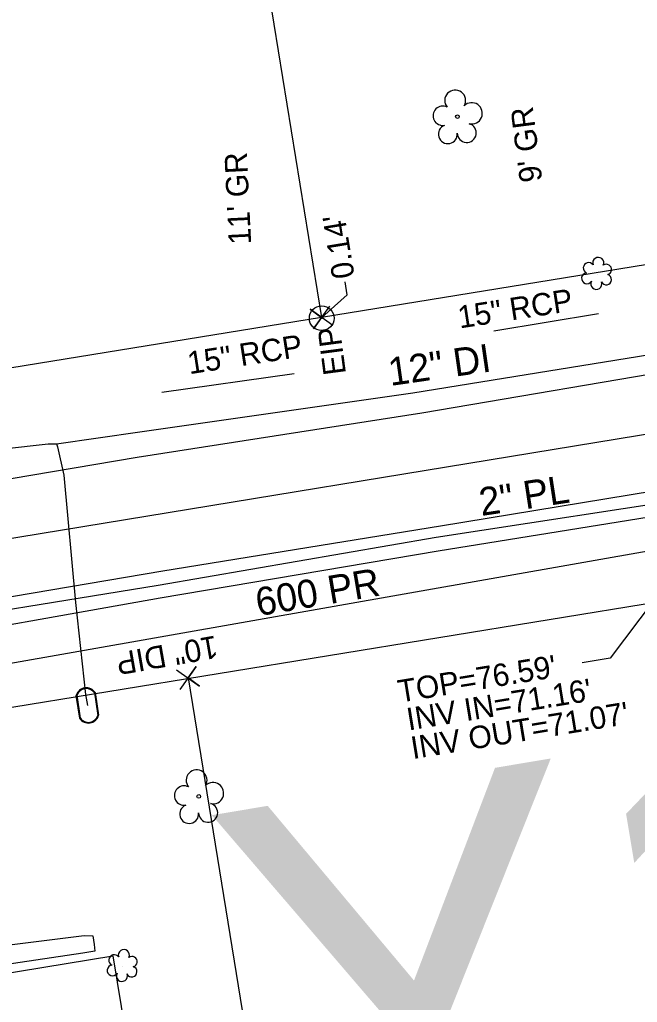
# Model space of a CAD drawing. Extents: x 2364404 to 2371833, y 798876 to 809754.
# Drawn here: x 2368683.2 to 2368793.3, y 807917.2 to 808092.3 of the extents above; entities that cross this region are included whole.
import ezdxf

# ---------------------------------------------------------------- set-up
doc = ezdxf.new("R2010")
doc.units = 0
for name, color, linetype in [('Exist Building', 7, 'Continuous'), ('Exist Horizontal Alignment Direction Label', 7, 'Continuous'), ('Exist Property Corner CELL', 7, 'Continuous'), ('Exist Property Iron Pin CELL', 7, 'Continuous'), ('Exist Property Iron Pin Text', 7, 'Continuous'), ('Exist Property Line', 7, 'Continuous'), ('Exist Property Line Leader', 7, 'Continuous'), ('Exist Property Line Text', 7, 'Continuous'), ('Exist Right of Way Line', 7, 'Continuous'), ('Exist Roads EOP', 7, 'Continuous'), ('Exist Roads Soil Text', 7, 'Continuous'), ('Exist Structure Minor Pipes RCP 15 Inch', 7, 'Continuous'), ('Exist Structure Minor Pipes RCP 15 Inch Text', 7, 'Continuous'), ('Exist Utilities Gas UG Line SUE LOS B', 7, 'Continuous'), ('Exist Utilities Gas UG Line SUE LOS B Text', 7, 'Continuous'), ('Exist Utilities Sanitary Sewer Manhole Leader', 7, 'Continuous'), ('Exist Utilities Sanitary Sewer Manhole Top Elevation', 7, 'Continuous'), ('Exist Utilities Sanitary Sewer UG Line', 7, 'Continuous'), ('Exist Utilities Sanitary Sewer UG Line Invert Elevation', 7, 'Continuous'), ('Exist Utilities Sanitary Sewer UG Line Text', 7, 'Continuous'), ('Exist Utilities Telephone UG Cable SUE LOS C', 7, 'Continuous'), ('Exist Utilities Telephone UG Cable SUE LOS C Text', 7, 'Continuous'), ('Exist Utilities Water Meter CELL', 7, 'Continuous'), ('Exist Utilities Water UG Line SUE LOS B', 7, 'Continuous'), ('Exist Utilities Water UG Line SUE LOS B Text', 7, 'Continuous'), ('Exist Vegetation Hedge Row', 7, 'Continuous'), ('Exist Vegetation Shrub CELL', 7, 'Continuous'), ('Exist Vegetation Tree CELL', 7, 'Continuous'), ('Prop Horizontal Alignment', 7, 'Continuous')]:
    doc.layers.add(name, color=color, linetype=linetype)

msp = doc.modelspace()

# ---------------------------------------------------------------- linework, layer by layer
at = {"layer": 'Exist Building'}
msp.add_lwpolyline([(2368704.34, 807898.02), (2368640.13, 807887.48), (2368635.66, 807914.69), (2368658.33, 807918.42), (2368657.75, 807921.93), (2368674.26, 807924.65), (2368674.8, 807921.37), (2368699.83, 807925.48)], close=True, dxfattribs=at)
at = {"layer": 'Exist Property Corner CELL'}
for p, q in [((2368737.05, 808039.21), (2368737.05, 808039.21)), ((2368713.24, 807974.97), (2368713.24, 807974.97))]:
    msp.add_line(p, q, dxfattribs=at)
for points in [[(2368739.08, 808037.75), (2368735.02, 808040.67), (2368737.05, 808039.21), (2368735.59, 808037.18), (2368738.51, 808041.24)], [(2368711.21, 807976.43), (2368715.27, 807973.51), (2368713.24, 807974.97), (2368714.7, 807977), (2368711.78, 807972.94)]]:
    msp.add_lwpolyline(points, dxfattribs=at)
at = {"layer": 'Exist Property Iron Pin CELL'}
for radius in [2.2, 0.0707]:
    msp.add_circle((2368737.07, 808039.07), radius, dxfattribs=at)
at = {"layer": 'Exist Property Line'}
for p, q in [((2368696.87, 808285.98), (2368737.05, 808039.21)), ((2368737.05, 808039.21), (2368737.07, 808039.07)), ((2368713.24, 807974.97), (2368748.74, 807757.77))]:
    msp.add_line(p, q, dxfattribs=at)
at = {"layer": 'Exist Property Line Leader'}
msp.add_lwpolyline([(2368737.09, 808039.23), (2368741.62, 808043.26), (2368741.25, 808045.55)], dxfattribs=at)
at = {"layer": 'Exist Right of Way Line'}
for p, q in [((2368966.1, 808076.49), (2368408.25, 807985.69)), ((2368975.69, 808017.56), (2368415.81, 807926.44))]:
    msp.add_line(p, q, dxfattribs=at)
at = {"layer": 'Exist Roads EOP'}
for points in [[(2368541.68, 807987.78), (2368591.98, 807995.84), (2368655.32, 808006.07), (2368704.17, 808014.3), (2368754.94, 808022.2), (2368804.52, 808030.63), (2368845.71, 808037.37), (2368893.98, 808045.18)], [(2368496.73, 807956.25), (2368544.8, 807964.78), (2368595.22, 807974.76), (2368620.07, 807978.44), (2368644.18, 807982.77), (2368658.61, 807985.55), (2368708.73, 807994.07), (2368758.23, 808002.08), (2368808.85, 808010.39), (2368820.54, 808011.83), (2368846.02, 808015.63), (2368897.31, 808024.64)]]:
    msp.add_lwpolyline(points, dxfattribs=at)
at = {"layer": 'Exist Structure Minor Pipes RCP 15 Inch'}
for p, q in [((2368767.76, 808036.8), (2368786.44, 808039.92)), ((2368732.19, 808029.17), (2368708.58, 808025.86))]:
    msp.add_line(p, q, dxfattribs=at)
at = {"layer": 'Exist Utilities Gas UG Line SUE LOS B'}
msp.add_lwpolyline([(2368407.49, 807900.26), (2368407.83, 807902.19), (2368408.5, 807903.92), (2368408.48, 807906.42), (2368409.65, 807914.64), (2368412.56, 807921.31), (2368413.42, 807922.79), (2368414.43, 807924.35), (2368420.02, 807930.36), (2368432.93, 807938.29), (2368511.16, 807956.83), (2368547.75, 807963.81), (2368550.91, 807964.29), (2368560.32, 807966.83), (2368577.66, 807970.81), (2368609.45, 807976.23), (2368658.87, 807983.56), (2368707.95, 807991.52), (2368757.5, 808000.06), (2368807.07, 808007.66), (2368820.71, 808009.46), (2368856.81, 808014.26), (2368905.45, 808022.91)], dxfattribs=at)
at = {"layer": 'Exist Utilities Sanitary Sewer Manhole Leader'}
msp.add_lwpolyline([(2368804.16, 807999.27), (2368788.52, 807978.49), (2368783.51, 807977.67)], dxfattribs=at)
at = {"layer": 'Exist Utilities Sanitary Sewer UG Line'}
msp.add_line((2368448.77, 807936.62), (2368803.21, 807999.04), dxfattribs=at)
at = {"layer": 'Exist Utilities Telephone UG Cable SUE LOS C'}
msp.add_lwpolyline([(2368614.19, 807962.49), (2368614.48, 807964.11), (2368617.51, 807973.27), (2368659.45, 807980.57), (2368708.28, 807989.23), (2368757.83, 807997.6), (2368804.31, 808005.12), (2368807.97, 807999.56), (2368809.5, 807994.04), (2368810.63, 807992.57), (2368810.63, 807992.57), (2368811.3, 807991)], dxfattribs=at)
at = {"layer": 'Exist Utilities Water Meter CELL'}
msp.add_line((2368695.31, 807970.08), (2368695.31, 807970.08), dxfattribs=at)
for points in [[(2368693.93, 807967.81), (2368693.32, 807971.87)], [(2368694.07, 807967.83), (2368693.46, 807971.89)], [(2368696.55, 807972.33), (2368697.16, 807968.3)], [(2368696.69, 807972.35), (2368697.3, 807968.32)]]:
    msp.add_lwpolyline(points, dxfattribs=at)
for centre, radius, start, end in [((2368695.11, 807971.37), 1.86, 31.7443, 164.5457), ((2368695.11, 807971.36), 1.73, 33.8672, 162.3486), ((2368695.5, 807968.8), 1.86, 212.2146, 344.8747), ((2368695.51, 807968.79), 1.73, 213.6935, 343.4391)]:
    msp.add_arc(centre, radius, start, end, dxfattribs=at)
at = {"layer": 'Exist Utilities Water UG Line SUE LOS B'}
for points in [[(2368680.36, 808015.78), (2368688.31, 808016.66), (2368689.77, 808016.7), (2368704.64, 808018.8), (2368753.33, 808025.79), (2368803.62, 808033.92), (2368810.16, 808035.08), (2368853.48, 808041.6), (2368865.07, 808043.43), (2368901.86, 808048.89)], [(2368689.77, 808016.7), (2368689.98, 808016.15), (2368691.11, 808011.09), (2368693.17, 807988.41), (2368694.94, 807972.03), (2368695.31, 807970.08)]]:
    msp.add_lwpolyline(points, dxfattribs=at)
at = {"layer": 'Exist Vegetation Hedge Row'}
msp.add_lwpolyline([(2368656.22, 807925.92), (2368671.88, 807928.41), (2368673.37, 807928.15), (2368675.66, 807926.13), (2368677.58, 807926.92), (2368694.72, 807929.1), (2368696.28, 807929.04), (2368696.5, 807927.5), (2368696.62, 807926.31), (2368694.49, 807925.93), (2368677.67, 807923.43), (2368675.45, 807925.45), (2368658.21, 807922.85), (2368656.26, 807921.53), (2368655.31, 807921.7), (2368654.71, 807923.45), (2368654.63, 807924.61), (2368656.22, 807925.92)], dxfattribs=at)
at = {"layer": 'Exist Vegetation Shrub CELL'}
for p, q in [((2368786.15, 808046.89), (2368786.15, 808046.89)), ((2368701.58, 807923.56), (2368701.58, 807923.56))]:
    msp.add_line(p, q, dxfattribs=at)
for centre, radius, start, end in [((2368784.67, 808048.01), 0.968, 35.8908, 245.4216), ((2368786.38, 808048.93), 0.99, 334.8391, 200.4717), ((2368787.82, 808047.75), 0.929, 284.4567, 126.0861), ((2368784.35, 808046.18), 0.955, 95.1099, 327.9534), ((2368787.79, 808045.96), 0.937, 204.9913, 73.4601), ((2368786.02, 808045.2), 0.984, 151.2797, 21.387), ((2368701.81, 807925.6), 0.99, 334.8391, 200.4717), ((2368700.09, 807924.68), 0.968, 35.8908, 245.4216), ((2368703.25, 807924.42), 0.929, 284.4567, 126.0861), ((2368699.78, 807922.85), 0.955, 95.1099, 327.9534), ((2368701.45, 807921.87), 0.984, 151.2797, 21.387), ((2368703.21, 807922.63), 0.937, 204.9913, 73.4601)]:
    msp.add_arc(centre, radius, start, end, dxfattribs=at)
at = {"layer": 'Exist Vegetation Tree CELL'}
for p, q in [((2368761.26, 808074.99), (2368761.26, 808074.99)), ((2368715.15, 807953.85), (2368715.15, 807953.85))]:
    msp.add_line(p, q, dxfattribs=at)
for centre in [(2368761.26, 808074.99), (2368715.15, 807953.85)]:
    msp.add_circle(centre, 0.326, dxfattribs=at)
for centre, radius, start, end in [((2368760.87, 808077.87), 1.86, 330.1651, 219.7134), ((2368758.65, 808075.15), 1.73, 62.6636, 279.3457), ((2368763.81, 808075.58), 1.9, 257.1011, 134.1999), ((2368759.56, 808071.87), 1.69, 111.5671, 6.231), ((2368762.93, 808072.09), 1.7, 181.2822, 74.56), ((2368714.77, 807956.73), 1.86, 330.1651, 219.7134), ((2368712.55, 807954.01), 1.73, 62.6636, 279.3457), ((2368717.7, 807954.44), 1.9, 257.1011, 134.1999), ((2368713.45, 807950.73), 1.69, 111.5671, 6.231), ((2368716.83, 807950.95), 1.7, 181.2822, 74.56)]:
    msp.add_arc(centre, radius, start, end, dxfattribs=at)
at = {"layer": 'Prop Horizontal Alignment'}
msp.add_line((2368381.6, 807950.7), (2368895.64, 808034.91), dxfattribs=at)

# ---------------------------------------------------------------- texts
at = {"layer": 'Exist Horizontal Alignment Direction Label'}
msp.add_text('-Y15-', height=73.5, rotation=9.4942, dxfattribs=at).set_placement((2368695.22, 807872.27))
at = {"layer": 'Exist Property Iron Pin Text'}
msp.add_text('EIP', height=4, rotation=97.4798, dxfattribs=at).set_placement((2368741.41, 808029.2))
at = {"layer": 'Exist Property Line Text'}
msp.add_text("0.14'", height=4, rotation=99.2482, dxfattribs=at).set_placement((2368742.97, 808046.46))
at = {"layer": 'Exist Roads Soil Text'}
for s, rotation, p in [("9' GR", 97.3665, (2368776.41, 808063.56)), ("11' GR", 92.7743, (2368724.51, 808052.28))]:
    msp.add_text(s, height=4, rotation=rotation, dxfattribs=at).set_placement(p)
at = {"layer": 'Exist Structure Minor Pipes RCP 15 Inch Text'}
for p in [(2368761.67, 808037.24), (2368713.49, 808029.08)]:
    msp.add_text('15" RCP', height=4, rotation=8.8742, dxfattribs=at).set_placement(p)
at = {"layer": 'Exist Utilities Gas UG Line SUE LOS B Text'}
msp.add_text('2" PL', height=5, rotation=8.7175, dxfattribs=at).set_placement((2368765.54, 808003.82))
at = {"layer": 'Exist Utilities Sanitary Sewer Manhole Top Elevation'}
msp.add_text("TOP=76.59'", height=4, rotation=9.2445, dxfattribs=at).set_placement((2368750.99, 807970.57))
at = {"layer": 'Exist Utilities Sanitary Sewer UG Line Invert Elevation'}
for s, p in [("INV IN=71.16'", (2368752.56, 807965.6)), ("INV OUT=71.07'", (2368753.31, 807960.5))]:
    msp.add_text(s, height=4, rotation=9.2445, dxfattribs=at).set_placement(p)
at = {"layer": 'Exist Utilities Sanitary Sewer UG Line Text'}
msp.add_text('10" DIP', height=4, rotation=189.9874, dxfattribs=at).set_placement((2368718.14, 807982.55))
at = {"layer": 'Exist Utilities Telephone UG Cable SUE LOS C Text'}
msp.add_text('600 PR', height=5, rotation=9.587, dxfattribs=at).set_placement((2368725.74, 807985.97))
at = {"layer": 'Exist Utilities Water UG Line SUE LOS B Text'}
msp.add_text('12" DI', height=5, rotation=8.1706, dxfattribs=at).set_placement((2368749.32, 808027))

doc.saveas('drawing.dxf')
